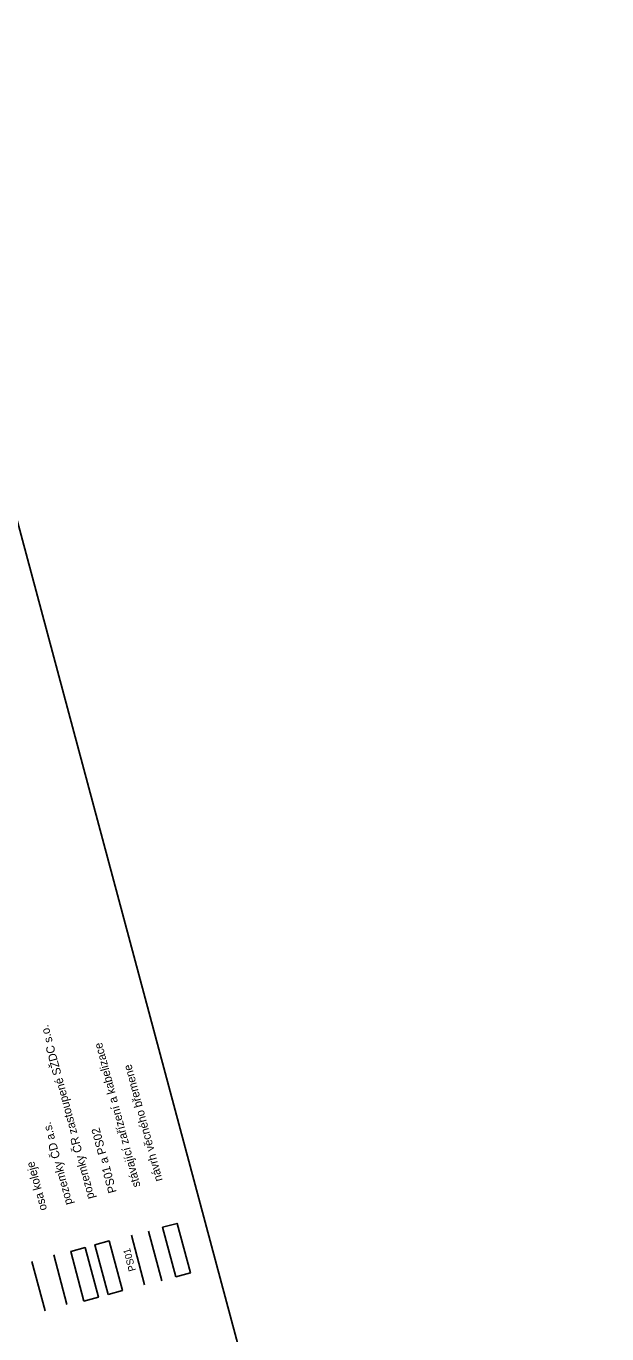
# Model space of a CAD drawing. Extents: x -754710 to -754206, y -1169123 to -1168234.
# Drawn here: x -754380.5 to -754205.7, y -1168628 to -1168234.4 of the extents above; entities that cross this region are included whole.
import ezdxf

# ---------------------------------------------------------------- set-up
doc = ezdxf.new("R2010")
doc.units = 0
for name, color, linetype in [('Vrstva 1', 7, 'Continuous'), ('Vrstva 10', 7, 'Continuous'), ('Vrstva 3', 7, 'Continuous'), ('Vrstva 61', 7, 'Continuous')]:
    doc.layers.add(name, color=color, linetype=linetype)

msp = doc.modelspace()

# ---------------------------------------------------------------- linework, layer by layer
at = {"layer": 'Vrstva 1'}
msp.add_line((-754368.21, -1168619.11), (-754372.22, -1168604.18), dxfattribs=at)
at = {"layer": 'Vrstva 10'}
msp.add_lwpolyline([(-754335.42, -1168610.8), (-754339.43, -1168595.87), (-754335.08, -1168594.71), (-754331.08, -1168609.64)], close=True, dxfattribs=at)
at = {"layer": 'Vrstva 3'}
for p, q in [((-754339.71, -1168612.01), (-754343.71, -1168597.07)), ((-754344.84, -1168613.21), (-754348.84, -1168598.27)), ((-754374.78, -1168621.07), (-754378.78, -1168606.14))]:
    msp.add_line(p, q, dxfattribs=at)
for points in [[(-754710.01, -1168311.22), (-754492.6, -1169122.6), (-754205.72, -1169045.73), (-754423.13, -1168234.35)], [(-754363.1, -1168618.09), (-754367.1, -1168603.16), (-754362.76, -1168601.99), (-754358.75, -1168616.93)], [(-754355.86, -1168616.09), (-754359.86, -1168601.16), (-754355.52, -1168600), (-754351.52, -1168614.93)]]:
    msp.add_lwpolyline(points, close=True, dxfattribs=at)
at = {"layer": 'Vrstva 61'}
msp.add_lwpolyline([(-754492.6, -1169122.6), (-754205.72, -1169045.73), (-754423.13, -1168234.35), (-754710.01, -1168311.22)], dxfattribs=at)

# ---------------------------------------------------------------- texts
at = {"layer": 'Vrstva 3'}
for s, height, rotation, p in [('pozemky ČR zastoupené SŽDC s.o.', 2.52, 105.021, (-754359.87, -1168587.02)), ('stávající zařízení a kabelizace', 2.52, 105.021, (-754346.08, -1168583.5)), ('návrh věcného břemene', 2.52, 105.021, (-754339.44, -1168581.73)), ('pozemky ČD a.s.', 2.52, 105.021, (-754366.51, -1168588.79)), ('PS01 a PS02 ', 2.52, 105.021, (-754353.24, -1168585.24)), ('osa koleje', 2.52, 105.021, (-754374.19, -1168590.5)), ('PS01', 2.16, 105, (-754347.46, -1168608.83))]:
    msp.add_text(s, height=height, rotation=rotation, dxfattribs=at).set_placement(p)

doc.saveas('drawing.dxf')
